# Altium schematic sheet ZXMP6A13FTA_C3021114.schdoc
size 127 x 101 mm
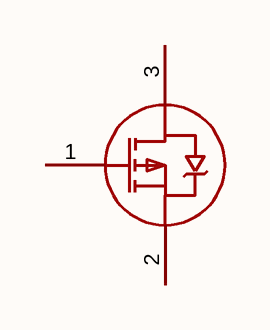
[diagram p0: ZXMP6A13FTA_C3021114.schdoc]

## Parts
Q?  zxmp6a13fta  [SOT-23_L2.9-W1.3-P1.90-LS2.4-BR]  (value not drawn)

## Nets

Not connected (* = marked no-connect by the designer): Q? 1(G) 2(S) 3(D)

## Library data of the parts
Q? = zxmp6a13fta: 数量:1个P沟道;漏源电压(Vdss):60V;连续漏极电流(Id):1.6A;导通电阻(RDS(on)):240mΩ@4.5V;耗散功率(Pd):1.5W;阈值电压(Vgs(th)):2.6V;; Manufacturer: TECH PUBLIC(台舟); Symbol: ZXMP6A13FTA_C3021114; AddInBom: yes; ModelId: c62791f0466c4ae2a892c056b845b0ca; ModelName: SOT-23-3P_L2.9-W1.3-H1.0-LS2.4-P0.95; ModelTransform: 98.64468,114.173,0,180,0,0,0.001,-0.002,0; Number: 1个P沟道; Drain to Source Voltage: 60V; Current - Continuous Drain(Id): 1.6A; Pd - Power Dissipation: 1.5W; Gate Threshold Voltage (Vgs(th)): 2.6V; Gate Charge(Qg): 11.3nC@10V; Input Capacitance(Ciss): 444.2pF; Reverse Transfer Capacitance (Crss@Vds): 17.9pF; Type: P沟道; Output Capacitance(Coss): 19.6pF; Vgs: ±20V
